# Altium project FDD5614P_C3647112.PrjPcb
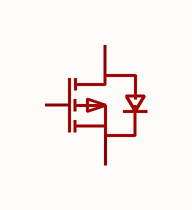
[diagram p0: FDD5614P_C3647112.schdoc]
1 sheet, 1 parts. Net scope: global (net labels, ports and power ports of the same name join across sheets).

## Sheet FDD5614P_C3647112.schdoc
size 127 x 101 mm

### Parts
Q?  fdd5614p_c3647112  [TO-252-2_L6.6-W6.0-P4.58-LS10.1-BR]  (value not drawn)

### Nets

Not connected (* = marked no-connect by the designer): Q? 1(G) 2(D) 3(S)

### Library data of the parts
Q? = fdd5614p_c3647112: 数量:1个P沟道;漏源电压(Vdss):60V;连续漏极电流(Id):15A;导通电阻(RDS(on)):75mΩ@10V;耗散功率(Pd):40W;阈值电压(Vgs(th)):1.6V;; Manufacturer: MSKSEMI(美森科); AddInBom: yes; ModelId: 15201b043553414fa3153da7281ca125; ModelTransform: 259.842,395.6685,0,90,0,0,-38.543,0,0; Number: 1个P沟道; Drain to Source Voltage: 60V; Current - Continuous Drain(Id): 15A; Pd - Power Dissipation: 40W; Gate Threshold Voltage (Vgs(th)): 1.6V; Gate Charge(Qg): 16.4nC@10V; Input Capacitance(Ciss): 870pF; Reverse Transfer Capacitance (Crss@Vds): 42pF; Type: P沟道; Output Capacitance(Coss): 70pF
